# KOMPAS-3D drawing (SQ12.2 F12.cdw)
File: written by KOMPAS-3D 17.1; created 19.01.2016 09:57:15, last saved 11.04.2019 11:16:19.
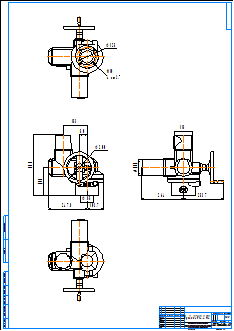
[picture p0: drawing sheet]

Sheet 1: A1, portrait

Title block, sheet 1: name: Привод SQ12.2 F12; material: Внимание! Данный продукт является объектом авторского права ООО «Торговый Дом АДЛ». / Запрещается изменение, копирование, распространение / (в том числе путем копирования на другие сайты и ресурсы в Интернете) / или любое иное использование информации и объектов без предварительного / согласия правообладателя (ООО «Торговый Дом АДЛ»).; sheets: 1; organisation: ООО "Торговый дом АДЛ"; sheet format: A1; stored path: \\adlc.lan\data\АДЛ_ПКД\3D-модели\Поставщики\Сервоприводы AUMA\Электроприводы серии SQ\KOMPAS 2D\SQ12.2 F12.cdw

Views: Проекционный вид 2, Проекционный вид 3, Проекционный вид 4
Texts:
  Klimkovich
  ADL
Dimensions and other numbers on the sheet: 385; 153; 200; 175; 103,7; 247,8; 50; 85; 1 1; 253,7; 264; 115; 101; 125; 4 отв.; 1:2,5; 1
